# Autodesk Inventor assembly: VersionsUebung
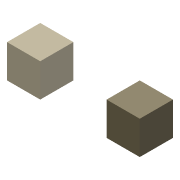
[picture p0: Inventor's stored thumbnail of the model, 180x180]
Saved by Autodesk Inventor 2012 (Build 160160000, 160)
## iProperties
Created: 2004-10
Part Number: VersionsUebung
Document SubType Name: Assembly
Designer: jukr
Manufacturer: Standard
Standards Organization: Custom
Author: jukr
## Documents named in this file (3)
- C:\Daten Vault 2012 Inventor\Kapitel 6\6.6\VersionsUebung\VersionsUebung.iam
- C:\Daten Vault 2012 Inventor\Kapitel 6\6.6\VersionsUebung\Vers Teil 1.ipt
- C:\Daten Vault 2012 Inventor\Kapitel 6\6.6\VersionsUebung\Vers Teil 2.ipt
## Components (2 placed, 2 different names)
1. Vers Teil 1:1 — Fluchtend:1, Fluchtend:2
2. Vers Teil 2:1 — Fluchtend:1, Fluchtend:2
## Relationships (2: Flush 2)
- Fluchtend:1 [Flush]: Vers Teil 1:1 ↔ Vers Teil 2:1
- Fluchtend:2 [Flush]: Vers Teil 1:1 ↔ Vers Teil 2:1
